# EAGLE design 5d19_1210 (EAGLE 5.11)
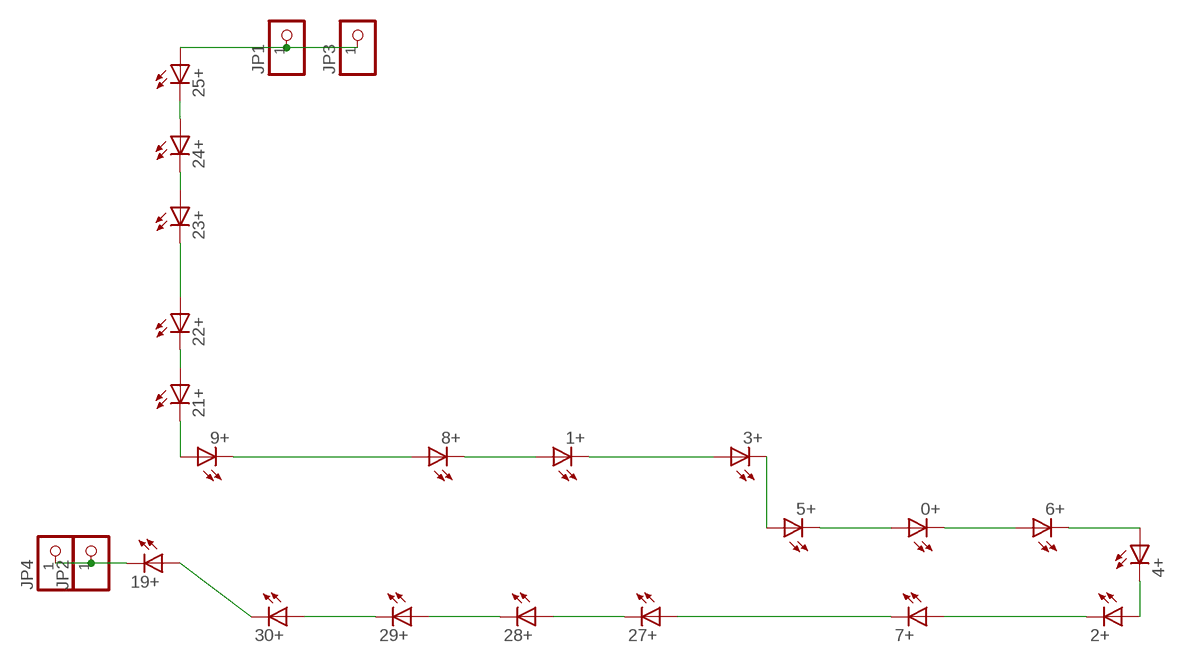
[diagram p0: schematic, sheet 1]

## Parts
0+  LED1210  [1210]
1+  LED1210  [1210]
2+  LED1210  [1210]
3+  LED1210  [1210]
4+  LED1210  [1210]
5+  LED1210  [1210]
6+  LED1210  [1210]
7+  LED1210  [1210]
8+  LED1210  [1210]
9+  LED1210  [1210]
19+  LED1210  [1210]
21+  LED1210  [1210]
22+  LED1210  [1210]
23+  LED1210  [1210]
24+  LED1210  [1210]
25+  LED1210  [1210]
27+  LED1210  [1210]
28+  LED1210  [1210]
29+  LED1210  [1210]
30+  LED1210  [1210]
JP1  PINHD-1X11X0.4  [1X01]
JP2  PINHD-1X11X0.4  [1X01]
JP3  PINHD-1X11MM6  [1X1MM8]
JP4  PINHD-1X11MM6  [1X1MM8]

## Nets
MINUS: 19+.P$2(C) JP2.1 JP4.1
N$4: 19+.P$1(A) 30+.P$2(C)
N$6: 8+.P$1(A) 9+.P$2(C)
N$7: 29+.P$2(C) 30+.P$1(A)
N$8: 28+.P$2(C) 29+.P$1(A)
N$9: 27+.P$2(C) 28+.P$1(A)
N$12: 2+.P$2(C) 7+.P$1(A)
N$13: 7+.P$2(C) 27+.P$1(A)
N$14: 2+.P$1(A) 4+.P$2(C)
N$15: 4+.P$1(A) 6+.P$2(C)
N$16: 0+.P$2(C) 6+.P$1(A)
N$17: 0+.P$1(A) 5+.P$2(C)
N$18: 3+.P$2(C) 5+.P$1(A)
N$19: 1+.P$2(C) 3+.P$1(A)
N$20: 1+.P$1(A) 8+.P$2(C)
N$23: 9+.P$1(A) 21+.P$2(C)
N$24: 21+.P$1(A) 22+.P$2(C)
N$25: 22+.P$1(A) 23+.P$2(C)
N$26: 24+.P$1(A) 25+.P$2(C)
N$28: 23+.P$1(A) 24+.P$2(C)
PLUS: 25+.P$1(A) JP1.1 JP3.1

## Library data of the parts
0+ 1+ 2+ 3+ 4+ 5+ 6+ 7+ 8+ 9+ 19+ 21+ 22+ 23+ 24+ 25+ 27+ 28+ 29+ 30+ = led(2):LED: LED
JP1-JP4 = pinhead:PINHD-1X1: PIN HEADER

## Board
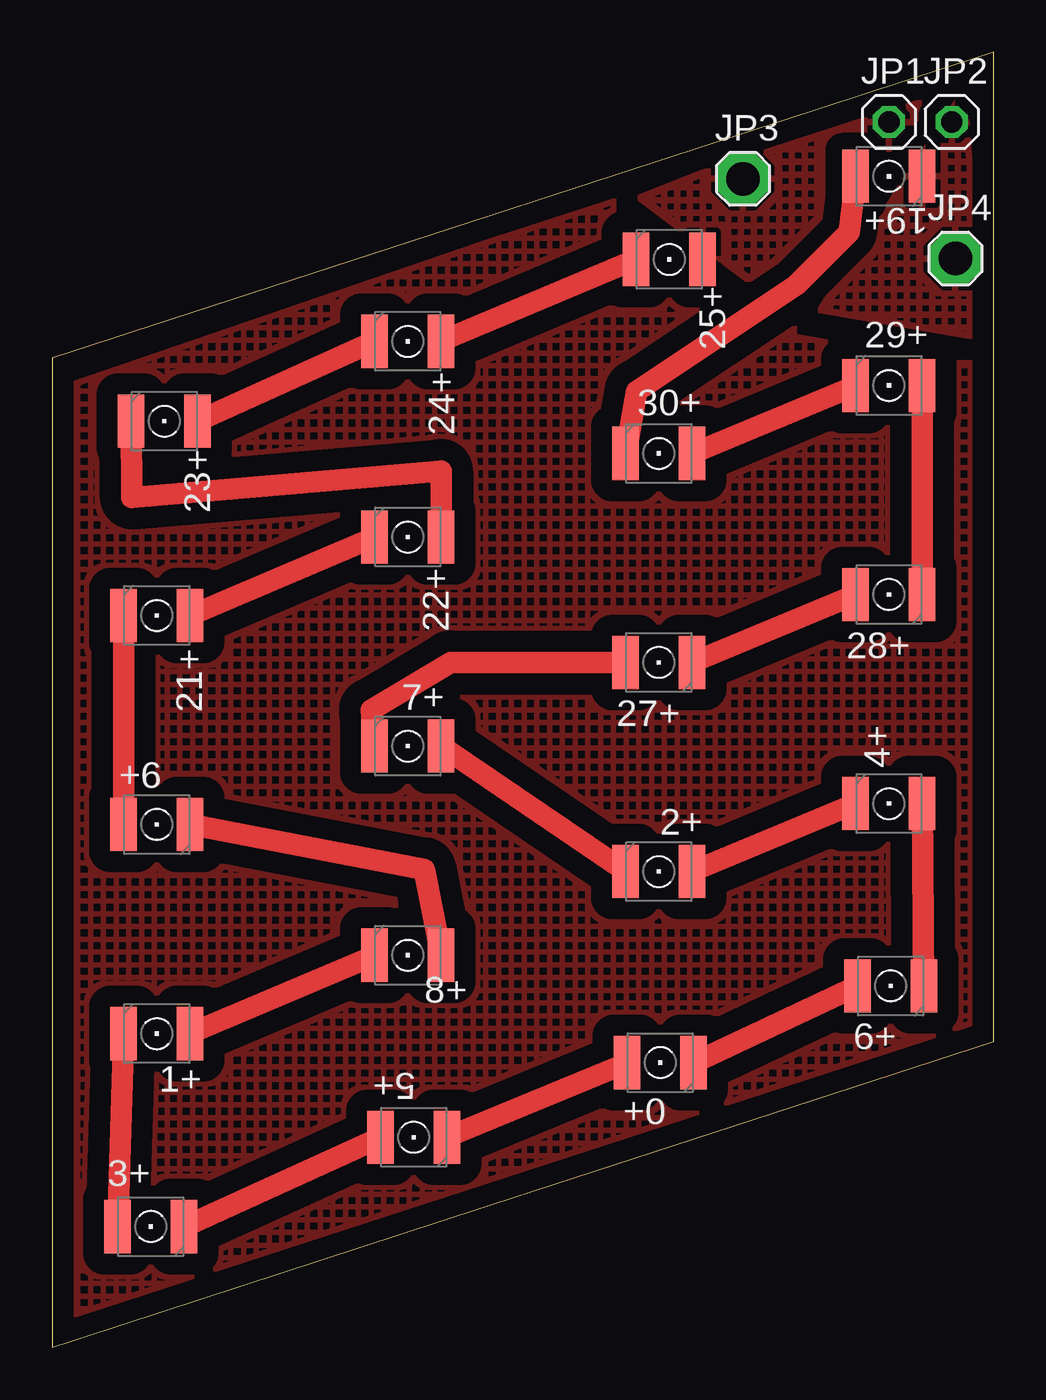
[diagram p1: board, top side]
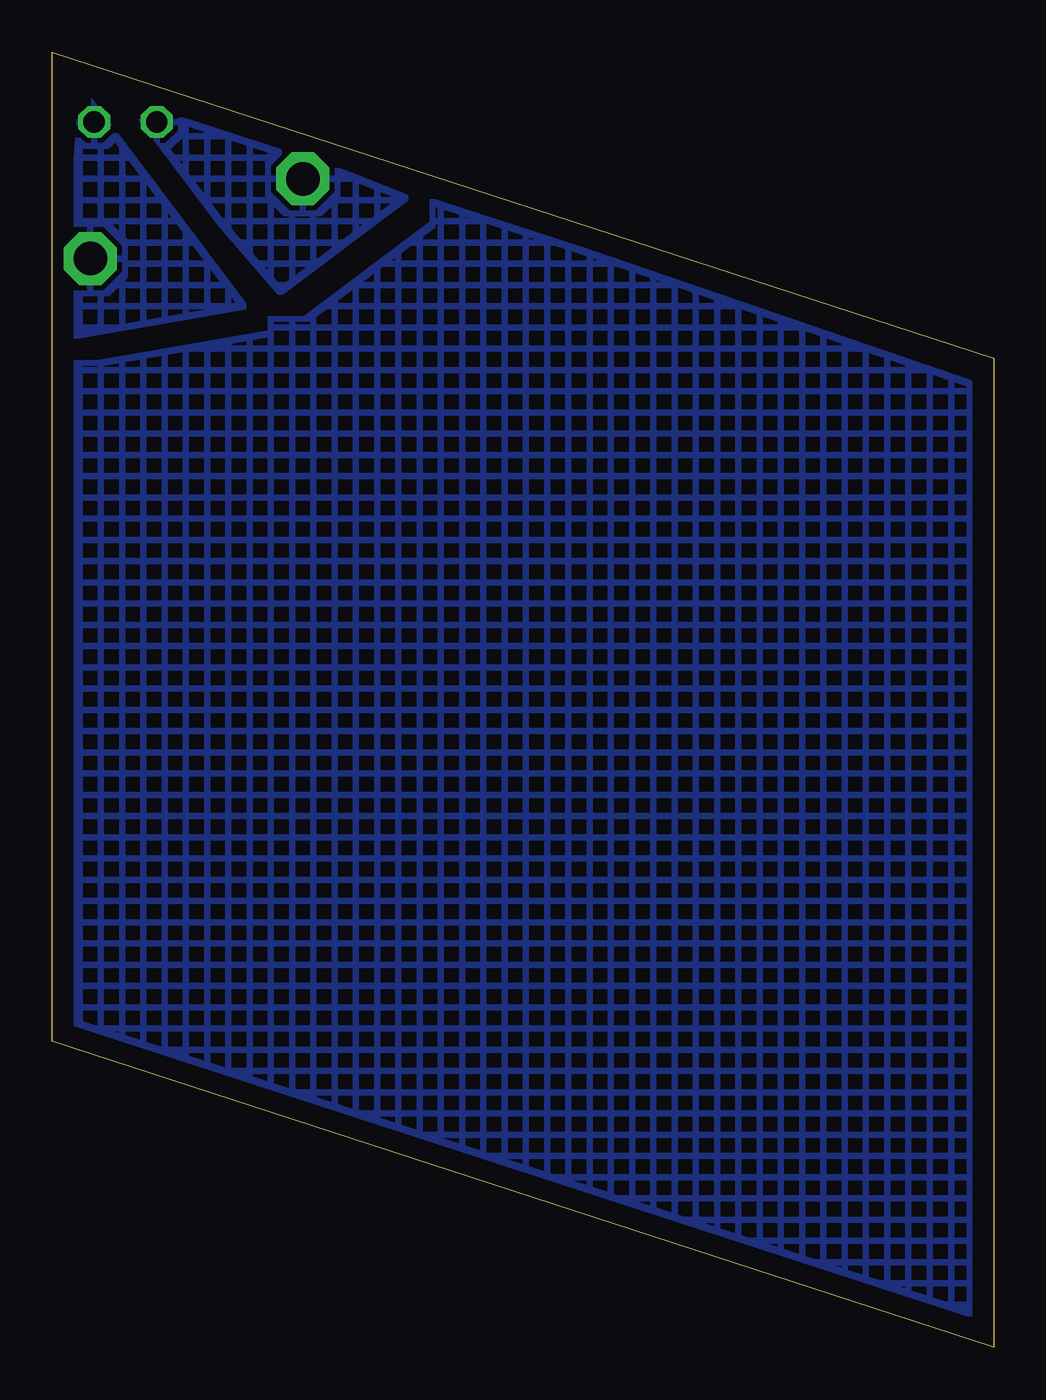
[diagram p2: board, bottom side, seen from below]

Size 45 x 61.94 mm. Coordinates in mm from the lower left corner, seen from the top.
Outline: 0,0 45,14.62 45,61.94 0,47.31 0,0
Copper layers (1*16): Top 0.035mm / dielectric 1.5mm / Bottom 0.035mm
Design rules "default": minimum track width 10mil, minimum drill 24mil, track to track 8mil, track to pad 8mil, pad to pad 8mil, via to via 8mil, smd to smd 8mil, copper to edge 40mil, drill to drill 8mil, minimum pad ring 10mil, minimum via ring 8mil, stop-mask expansion 4mil, vias tented up to drill 0mil, thermal gap 10mil

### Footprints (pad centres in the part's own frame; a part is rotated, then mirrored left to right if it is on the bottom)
1210 = smd 1.27 x 2.54: P$1 1.587,0; P$2 -1.587,0
1X01 = drill 1.016 octagon: 1 0,0
1X1MM8 = drill 1.6 pad 2.54 octagon: 1 0,0

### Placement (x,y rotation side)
0+  29.07,13.61 180 top
1+  5,15 0 top
2+  29,22.75 0 top
3+  4.71,5.77 180 top
4+  40,26 0 top
5+  17.28,10.04 180 top
6+  40.08,17.28 180 top
7+  17,28.75 0 top
8+  17,18.75 0 top
9+  5,25 180 top
19+  40,56 180 top
21+  5,35 0 top
22+  17,38.75 0 top
23+  5.36,44.29 0 top
24+  17,48.11 0 top
25+  29.5,52.03 0 top
27+  29,32.75 180 top
28+  40,36 180 top
29+  40,46 0 top
30+  29,42.75 0 top
JP1  40,58.6 0 top
JP2  43,58.6 0 top
JP3  33.02,55.88 0 top
JP4  43.18,52.07 0 top

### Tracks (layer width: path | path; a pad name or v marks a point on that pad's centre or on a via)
MINUS
  pour Top (isolate 0.813, rank 2, hatched): 43.6,60.11 36.69,49.6 44.45,48.26
  pour Bottom (isolate 0.813, rank 2, hatched): 43.6,60.11 35.79,49.78 44.45,48.26
N$1
  pour Top (isolate 1.016, rank 4, hatched): 0,45.72 0,0 44.45,15.24 44.45,60.96
  pour Bottom (isolate 1.016, rank 4, hatched): 0,45.72 0,0 44.45,15.24 44.45,60.96
N$4
  Top 1.016: 30+.P$2 27.94,45.72 35.56,50.8 38.1,53.34 19+.P$1
N$6
  Top 1.016: 8+.P$1 17.78,22.86 9+.P$2
N$7
  Top 1.016: 30+.P$1 29+.P$2
N$8
  Top 1.016: 28+.P$2 29+.P$1
N$9
  Top 1.016: 27+.P$2 28+.P$1
N$12
  Top 1.016: 7+.P$1 2+.P$2
N$13
  Top 1.016: 7+.P$2 15.24,30.48 19.05,32.75 27+.P$1
N$14
  Top 1.016: 2+.P$1 4+.P$2
N$15
  Top 1.016: 6+.P$2 4+.P$1
N$16
  Top 1.016: 0+.P$2 6+.P$1
N$17
  Top 1.016: 5+.P$2 0+.P$1
N$18
  Top 1.016: 3+.P$2 5+.P$1
N$19
  Top 1.016: 3+.P$1 1+.P$2
N$20
  Top 1.016: 1+.P$1 8+.P$2
N$23
  Top 1.016: 9+.P$1 21+.P$2
N$24
  Top 1.016: 21+.P$1 22+.P$2
N$25
  Top 1.016: 22+.P$1 18.59,41.91 3.81,40.64 23+.P$2
N$26
  Top 1.016: 24+.P$1 25+.P$2
N$28
  Top 1.016: 23+.P$1 24+.P$2
PLUS
  pour Top (isolate 0.813, rank 3, hatched): 43.18,60.96 34.09,50.43 28.06,54.98
  pour Bottom (isolate 0.813, rank 3, hatched): 43.18,60.96 34.09,50.43 28.06,54.98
